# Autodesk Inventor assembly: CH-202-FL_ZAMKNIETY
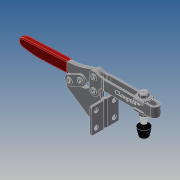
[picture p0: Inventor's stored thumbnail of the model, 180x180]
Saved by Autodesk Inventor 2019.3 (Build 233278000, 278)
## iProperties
Company: Î¢ÈíÖÐ¹ú
Created: 2011-05
Part Number: CH-202-FL_ZAMKNIETY
Material: Ogólny
Description: STEP AP203
Document SubType Name: Assembly
Designer: CADENGINEERING4
Sending System: SolidWorks 2010
Preprocessor: SwSTEP 2.0
Title: CH-202-FL.STEP
Author: Î¢ÈíÓÃ»§
Revision Number: ÈÎºÎ
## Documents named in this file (9)
- E:\STRONA\Horizontal toggle clamp\CH-202-FL\CH-202-FL_ZAMKNIETY.iam
- E:\STRONA\Horizontal toggle clamp\CH-202-FL\225-D-06.ipt
- E:\STRONA\Horizontal toggle clamp\CH-202-FL\56212-02.ipt
- E:\STRONA\Horizontal toggle clamp\CH-202-FL\FW516.ipt
- E:\STRONA\Horizontal toggle clamp\CH-202-FL\202-FL-02.ipt
- E:\STRONA\Horizontal toggle clamp\CH-202-FL\56212.ipt
- E:\STRONA\Horizontal toggle clamp\CH-202-FL\202-F-01.ipt
- E:\STRONA\Horizontal toggle clamp\CH-202-FL\203-F-04.ipt
- E:\STRONA\Horizontal toggle clamp\CH-202-FL\03.iam
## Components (14 placed, 14 different names)
1. 225-D-06_1 — Zestawiające:19, Zestawiające:20
2. 56212-02_2 — Równoległe:3, Zestawiające:2, Zestawiające:6
3. 225-D-06_3 — Zestawiające:23, Zestawiające:24, Zestawiające:26
4. FW516_4 — Równoległe:1, Równoległe:2, Zestawiające:1, Zestawiające:5, Zestawiające:6
5. 202-FL-02_5 — Równoległe:1, Zestawiające:5, Zestawiające:7, Zestawiające:9, Zestawiające:11, Zestawiające:12, Zestawiające:13, Zestawiające:23, Zestawiające:24, Zestawiające:25
6. 225-D-06_6 — Zestawiające:10, Zestawiające:12, Zestawiające:13
7. 225-D-06_7 — Zestawiające:21, Zestawiające:22, Zestawiające:27
8. FW516_8 — Równoległe:2, Zestawiające:3, Zestawiające:7, Zestawiające:8
9. 56212_9 — Równoległe:3, Zestawiające:1, Zestawiające:2, Zestawiające:3, Zestawiające:4, Zestawiające:9
10. 202-F-01_10 — Zestawiające:10, Zestawiające:11, Zestawiające:14, Zestawiające:15, Zestawiające:16, Zestawiające:17, Przejściowe:1
11. 203-F-04_11 — Zestawiające:14, Zestawiające:16, Zestawiające:18, Zestawiające:19, Zestawiające:20, Zestawiające:21, Zestawiające:22
12. 203-F-04_12 — Zestawiające:15, Zestawiające:17, Zestawiające:18
13. 03_13 [sub-assembly] — Zestawiające:25, Zestawiające:26, Zestawiające:27, Przejściowe:1
14. 56212-02_14 — Zestawiające:4, Zestawiające:8
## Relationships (31: Mate 27, Flush 3, Transitional 1)
- Równoległe:1 [Flush]: FW516_4 ↔ 202-FL-02_5
- Równoległe:2 [Flush]: FW516_4 ↔ FW516_8
- Równoległe:3 [Flush]: 56212-02_2 ↔ 56212_9
- Zestawiające:1 [Mate]: FW516_4 ↔ 56212_9
- Zestawiające:2 [Mate]: 56212-02_2 ↔ 56212_9
- Zestawiające:3 [Mate]: FW516_8 ↔ 56212_9
- Zestawiające:4 [Mate]: 56212_9 ↔ 56212-02_14
- Zestawiające:5 [Mate]: FW516_4 ↔ 202-FL-02_5
- Zestawiające:6 [Mate]: 56212-02_2 ↔ FW516_4
- Zestawiające:7 [Mate]: 202-FL-02_5 ↔ FW516_8
- Zestawiające:8 [Mate]: FW516_8 ↔ 56212-02_14
- Zestawiające:9 [Mate]: 202-FL-02_5 ↔ 56212_9
- Zestawiające:10 [Mate]: 225-D-06_6 ↔ 202-F-01_10
- Zestawiające:11 [Mate]: 202-FL-02_5 ↔ 202-F-01_10
- Zestawiające:12 [Mate]: 202-FL-02_5 ↔ 225-D-06_6
- Zestawiające:13 [Mate]: 202-FL-02_5 ↔ 225-D-06_6
- Zestawiające:14 [Mate]: 202-F-01_10 ↔ 203-F-04_11
- Zestawiające:15 [Mate]: 202-F-01_10 ↔ 203-F-04_12
- Zestawiające:16 [Mate]: 202-F-01_10 ↔ 203-F-04_11
- Zestawiające:17 [Mate]: 202-F-01_10 ↔ 203-F-04_12
- Zestawiające:18 [Mate]: 203-F-04_11 ↔ 203-F-04_12
- Zestawiające:19 [Mate]: 225-D-06_1 ↔ 203-F-04_11
- Zestawiające:20 [Mate]: 225-D-06_1 ↔ 203-F-04_11
- Zestawiające:21 [Mate]: 225-D-06_7 ↔ 203-F-04_11
- Zestawiające:22 [Mate]: 225-D-06_7 ↔ 203-F-04_11
- Zestawiające:23 [Mate]: 225-D-06_3 ↔ 202-FL-02_5
- Zestawiające:24 [Mate]: 225-D-06_3 ↔ 202-FL-02_5
- Zestawiające:25 [Mate]: 202-FL-02_5 ↔ 03_13
- Zestawiające:26 [Mate]: 225-D-06_3 ↔ 03_13
- Zestawiające:27 [Mate]: 225-D-06_7 ↔ 03_13
- Przejściowe:1 [Transitional]: 202-F-01_10 ↔ 03_13
